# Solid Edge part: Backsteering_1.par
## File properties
Author: KULL
Template: Iso Metric Part.par
Last saved by: KULL
Revision: 27
Application: Solid Edge
Accuracy: 0,990
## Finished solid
Body 1: solid body, 239 faces, 533 edges, 296 vertices.
  Faces by surface: cylinder 104, torus 63, plane 40, blend 27, sphere 5
  Edges by curve: circle 280, line 198, ellipse 28, intersection 26, curve on surface 1
Bounding box of the edges (mm; curved faces can reach further): 28.000 x 37.345 x 39.295, from (-5, -15.242, -19.6474) to (23, 22.1032, 19.6474).
Cylindrical faces by radius (mm): R0.2 x28, R0.8 x37, R1.3 x1, R1.8 x2, R2 x4, R3 x5, R4 x12, R5 x8, R6 x3, R8 x2, R9 x2
Toroidal faces (ring radius, tube radius in mm): R1 r0.2 x2, R1 r0.8 x2, R1.2 r0.8 x2, R1.5 r0.2 x2, R1.6 r0.2 x2, R1.7 r0.4 x1, R2.2 r0.8 x4, R2.4 r0.4 x2, R3.2 r0.2 x4, R3.2 r0.8 x2, R4.2 r0.2 x12, R4.2 r0.8 x4, R4.8 r0.2 x4, R4.8 r0.8 x4, R5.2 r0.8 x4, R5.8 r0.8 x4, R8.2 r0.2 x2, R8.8 r0.2 x2, R8.8 r0.8 x2, R9.8 r0.8 x2
Spherical faces by radius (mm): R0.8 x2, R3 x1, R4 x2
Planar faces by outward normal: +x 3, +y 5, +z 2, -x 4, -y 5, -z 2, oblique 19
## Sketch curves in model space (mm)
line (0, 0, 23) -> (0, 0, 11.1472)
line (-5.2801, 22, 0) -> (0.8486, 18.7374, 0)
circle centre (0, 0, -23) radius 4
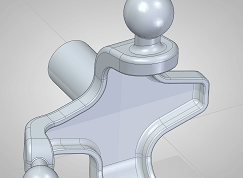
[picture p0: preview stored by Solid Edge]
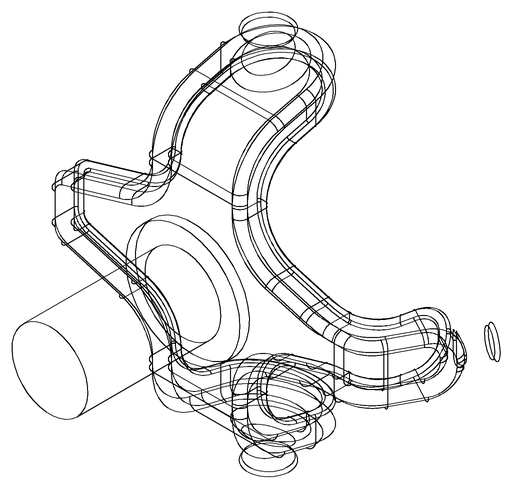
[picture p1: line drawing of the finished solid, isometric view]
